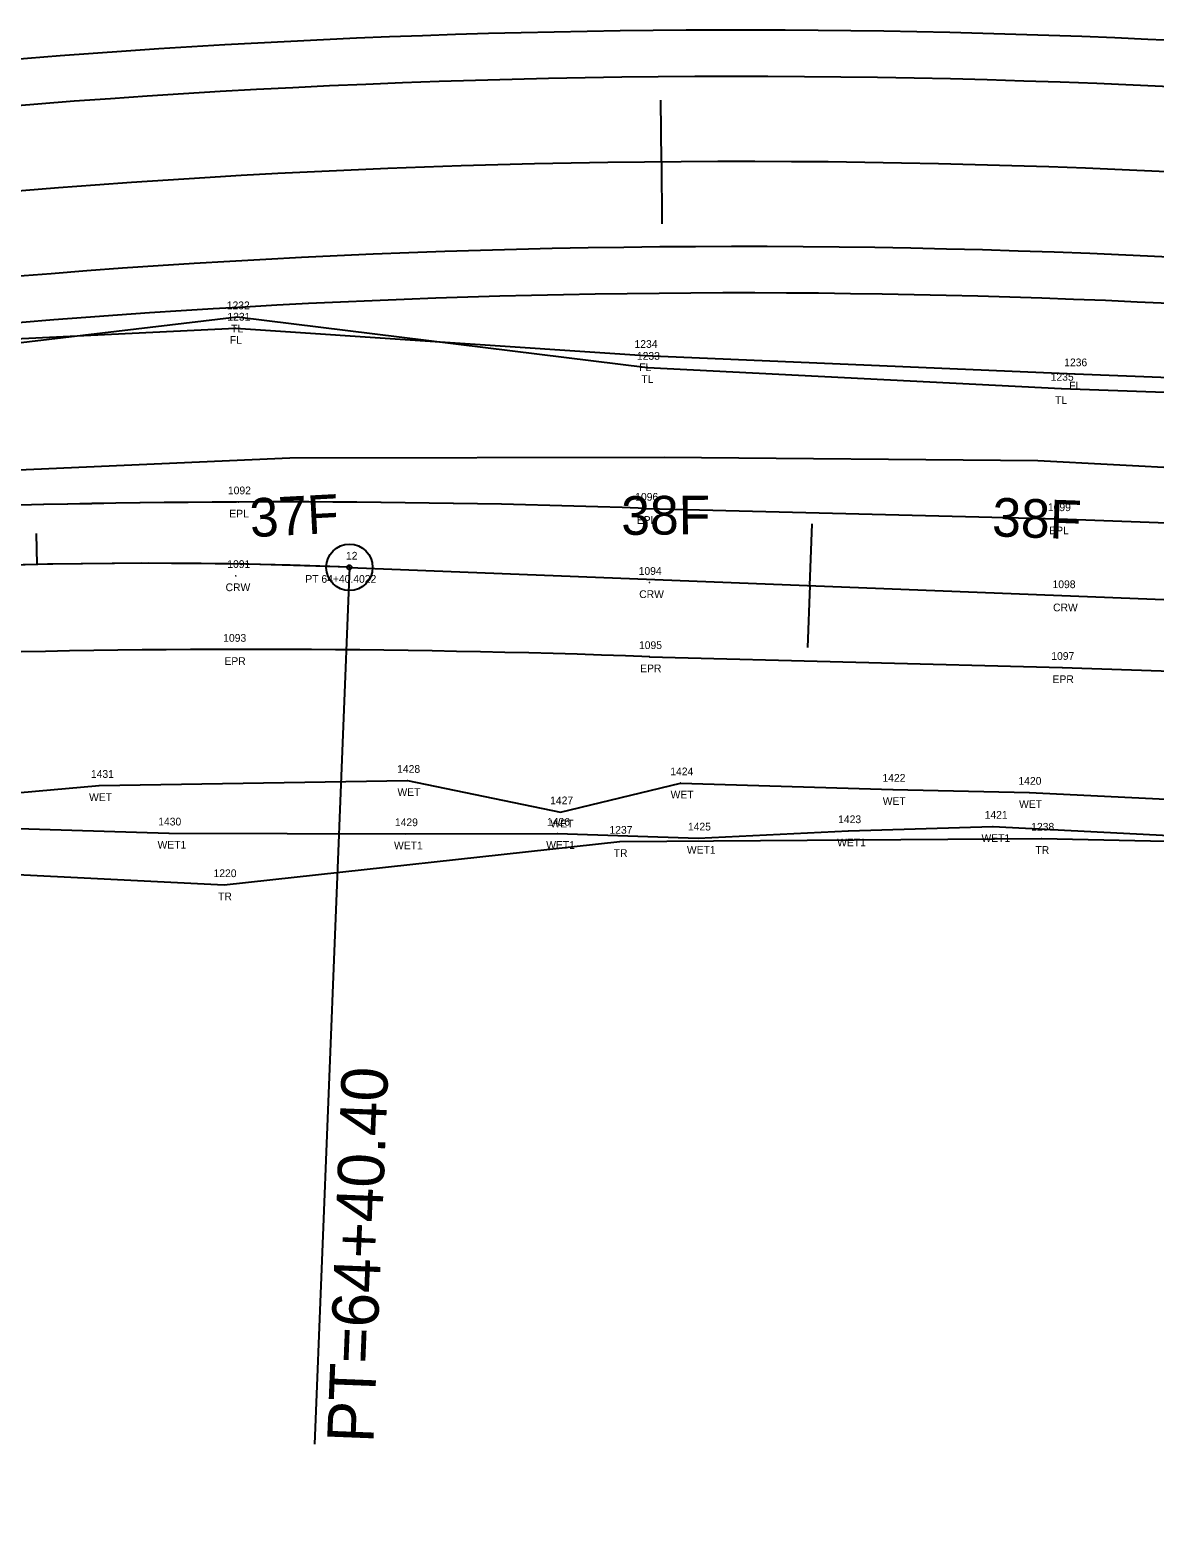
# Model space of a CAD drawing. Extents: x 1964982 to 1970452, y 1116335 to 1119906.
# Drawn here: x 1968079 to 1968224.5, y 1117805.4 to 1118000.4 of the extents above; entities that cross this region are included whole.
import ezdxf

# ---------------------------------------------------------------- set-up
doc = ezdxf.new("R2010")
doc.units = 0
for name, color, linetype in [('RD_EX_DV_Prop', 7, 'Continuous'), ('RD_EX_Fence_Other', 7, 'Continuous'), ('RD_EX_Fence_Other_txCode', 7, 'Continuous'), ('RD_EX_H2O_WetLd', 7, 'Continuous'), ('RD_EX_H2O_WetLd_txCode', 7, 'Continuous'), ('RD_EX_Road', 7, 'Continuous'), ('RD_EX_Road_txCode', 7, 'Continuous'), ('RD_EX_RW', 7, 'Continuous'), ('RD_EX_VEG', 7, 'Continuous'), ('RD_EX_VEG_txCode', 7, 'Continuous'), ('RD_HC_CL', 7, 'Continuous'), ('RD_HC_CL_Rel', 7, 'Continuous'), ('RD_HC_Data', 7, 'Continuous'), ('RD_HC_Data_Tic', 7, 'Continuous'), ('RD_HC_Data_Tic_Rel', 7, 'Continuous'), ('RD_HC_txCode', 7, 'Continuous'), ('RD_PD_CstnLmt', 7, 'Continuous'), ('RD_PD_Final_TrvlWay', 7, 'Continuous'), ('RD_PD_TX_CstnLmt', 7, 'Continuous'), ('RD_QTY_GR', 7, 'Continuous'), ('RD_SMD_Locator', 7, 'Continuous'), ('RD_SMD_Misc', 7, 'Continuous')]:
    doc.layers.add(name, color=color, linetype=linetype)

msp = doc.modelspace()

# ---------------------------------------------------------------- linework, layer by layer
at = {"layer": 'RD_EX_DV_Prop'}
msp.add_line((1968120.33, 1117930.94), (1968371.35, 1117920.98), dxfattribs=at)
msp.add_arc((1968094.39, 1117277.53), 653.93, 87.72663, 109.21172, dxfattribs=at)
at = {"layer": 'RD_EX_Fence_Other'}
msp.add_lwpolyline([(1967945.93, 1117995.37), (1967947.71, 1117952.52), (1967966.69, 1117955.54), (1968009.98, 1117960.51), (1968062.77, 1117959.8), (1968105.6, 1117961.86), (1968158.55, 1117958.33), (1968214.15, 1117955.95), (1968422.33, 1117947.89), (1968537.53, 1117942.88)], dxfattribs=at)
at = {"layer": 'RD_EX_H2O_WetLd'}
for points in [[(1967871.9, 1117823.22), (1967882.77, 1117820.95), (1967892.49, 1117817.57), (1967903.12, 1117821.47), (1967929.31, 1117838.9), (1967950.71, 1117852.83), (1967976.12, 1117865.5), (1968009.37, 1117883.81), (1968032.7, 1117893.9), (1968056.92, 1117899.97), (1968087.96, 1117902.71), (1968127.85, 1117903.36), (1968147.64, 1117899.29), (1968163.17, 1117903.04), (1968190.62, 1117902.21), (1968208.25, 1117901.82), (1968234.81, 1117900.5)], [(1967873.8, 1117813.35), (1967880.72, 1117811.81), (1967886.54, 1117810.11), (1967895.47, 1117810.58), (1967906.3, 1117816.05), (1967938.67, 1117833.57), (1967956.67, 1117840.55), (1967984.36, 1117856.79), (1968002.89, 1117867.52), (1968020.4, 1117877.91), (1968037.49, 1117884.16), (1968057.43, 1117895.18), (1968076.04, 1117897.19), (1968096.98, 1117896.55), (1968127.56, 1117896.46), (1968147.25, 1117896.52), (1968165.45, 1117895.9), (1968184.88, 1117896.85), (1968203.56, 1117897.42), (1968232.27, 1117895.94)]]:
    msp.add_lwpolyline(points, dxfattribs=at)
at = {"layer": 'RD_EX_Road'}
for points in [[(1968158.7, 1117938.56), (1968212.05, 1117937.21), (1968318.79, 1117933.28), (1968422.76, 1117929.93), (1968530.54, 1117925.7)], [(1968159.16, 1117919.37), (1968212.5, 1117917.97), (1968317.55, 1117914.44), (1968421.52, 1117910.75), (1968527.82, 1117906.41)]]:
    msp.add_lwpolyline(points, dxfattribs=at)
for centre, radius, start, end in [((1968111.4, 1116608.55), 1330.85, 87.96323, 92.25904), ((1968107.56, 1116504.27), 1416.05, 87.91148, 91.95976)]:
    msp.add_arc(centre, radius, start, end, dxfattribs=at)
at = {"layer": 'RD_EX_RW'}
for points in [[(1968158.7, 1117938.56), (1968212.05, 1117937.21), (1968318.79, 1117933.28), (1968422.76, 1117929.93), (1968530.54, 1117925.7)], [(1968159.16, 1117919.37), (1968212.5, 1117917.97), (1968317.55, 1117914.44), (1968421.52, 1117910.75), (1968527.82, 1117906.41)]]:
    msp.add_lwpolyline(points, dxfattribs=at)
for centre, radius, start, end in [((1968111.4, 1116608.55), 1330.85, 87.96323, 92.25762), ((1968107.56, 1116504.27), 1416.05, 87.91148, 91.95976)]:
    msp.add_arc(centre, radius, start, end, dxfattribs=at)
at = {"layer": 'RD_EX_VEG'}
for points in [[(1967422.03, 1117809.72), (1967453.38, 1117748.92), (1967559.8, 1117796.17), (1967844.47, 1117917.07), (1967917.86, 1117947.25), (1968009.67, 1117958.84), (1968061.48, 1117958.08), (1968105.8, 1117963.33), (1968158.86, 1117956.79), (1968212.37, 1117954.08), (1968423.16, 1117946.63), (1968536.42, 1117942.26)], [(1967303.54, 1117601.01), (1967338.99, 1117640.22), (1967353.28, 1117654.56), (1967394.76, 1117667.24), (1967484.61, 1117707.66), (1967711.58, 1117796.67), (1967890.09, 1117864.21), (1967929.29, 1117872.68), (1967959.15, 1117877.99), (1967976.93, 1117884.5), (1968014.32, 1117894.35), (1968104.14, 1117889.87), (1968155.31, 1117895.48), (1968209.85, 1117895.88), (1968320.55, 1117893.51), (1968423.04, 1117892.22), (1968529.15, 1117876.96)]]:
    msp.add_lwpolyline(points, dxfattribs=at)
at = {"layer": 'RD_HC_CL'}
msp.add_line((1968120.33, 1117930.94), (1969279.02, 1117884.95), dxfattribs=at)
msp.add_arc((1968094.39, 1117277.53), 653.93, 87.72663, 111.99584, dxfattribs=at)
at = {"layer": 'RD_HC_CL_Rel'}
msp.add_arc((1968170.83, 1116837.51), 1145.92, 84.66612, 115.04633, dxfattribs=at)
at = {"layer": 'RD_HC_Data'}
msp.add_line((1968120.33, 1117930.94), (1968115.83, 1117817.52), dxfattribs=at)
for radius in [3, 0.282]:
    msp.add_circle((1968120.33, 1117930.94), radius, dxfattribs=at)
at = {"layer": 'RD_HC_Data_Tic'}
for p, q in [((1968079.94, 1117931.3), (1968079.85, 1117935.3)), ((1968179.88, 1117928.58), (1968180.2, 1117936.57)), ((1968179.88, 1117928.58), (1968179.56, 1117920.59))]:
    msp.add_line(p, q, dxfattribs=at)
at = {"layer": 'RD_HC_Data_Tic_Rel'}
for q in [(1968160.61, 1117991.38), (1968160.75, 1117975.38)]:
    msp.add_line((1968160.68, 1117983.38), q, dxfattribs=at)
at = {"layer": 'RD_PD_CstnLmt'}
for p, q in [((1968064.24, 1117942.97), (1968112.64, 1117945.12)), ((1968112.64, 1117945.12), (1968161.02, 1117945.18)), ((1968161.02, 1117945.18), (1968209.35, 1117944.76)), ((1968209.35, 1117944.76), (1968257.63, 1117942.17))]:
    msp.add_line(p, q, dxfattribs=at)
at = {"layer": 'RD_PD_Final_TrvlWay'}
for radius in [1156.92, 1134.92]:
    msp.add_arc((1968170.83, 1116837.51), radius, 84.66612, 99.65724, dxfattribs=at)
at = {"layer": 'RD_QTY_GR'}
for radius, end in [(1162.92, 98.1201), (1128.92, 98.06898)]:
    msp.add_arc((1968170.83, 1116837.51), radius, 84.66612, end, dxfattribs=at)
at = {"layer": 'RD_SMD_Locator'}
for centre in [(1968105.8, 1117963.33), (1968105.6, 1117961.86), (1968158.55, 1117958.33), (1968158.86, 1117956.79), (1968214.15, 1117955.95), (1968212.37, 1117954.08), (1968105.99, 1117939.39), (1968158.7, 1117938.56), (1968212.05, 1117937.21), (1968120.33, 1117930.94), (1968105.63, 1117929.86), (1968159.12, 1117928.97), (1968212.65, 1117927.25), (1968105.39, 1117920.31), (1968159.16, 1117919.37), (1968212.5, 1117917.97), (1968087.96, 1117902.71), (1968127.85, 1117903.36), (1968163.17, 1117903.04), (1968190.62, 1117902.21), (1968208.25, 1117901.82), (1968147.64, 1117899.29), (1968096.98, 1117896.55), (1968127.56, 1117896.46), (1968147.25, 1117896.52), (1968165.45, 1117895.9), (1968184.88, 1117896.85), (1968203.56, 1117897.42), (1968209.85, 1117895.88), (1968155.31, 1117895.48), (1968104.14, 1117889.87)]:
    msp.add_circle(centre, 0.001, dxfattribs=at)

# ---------------------------------------------------------------- texts
at = {"layer": 'RD_EX_Fence_Other_txCode'}
for s, p in [('1231', (1968104.54, 1117962.86)), ('FL', (1968104.87, 1117959.86)), ('1234', (1968157.2, 1117959.33)), ('FL', (1968157.82, 1117956.33)), ('1236', (1968212.78, 1117956.95)), ('FL', (1968213.42, 1117953.95))]:
    msp.add_text(s, height=1, dxfattribs=at).set_placement(p)
at = {"layer": 'RD_EX_H2O_WetLd_txCode'}
for s, p in [('1431', (1968086.89, 1117903.71)), ('1428', (1968126.5, 1117904.36)), ('1424', (1968161.83, 1117904.04)), ('1422', (1968189.27, 1117903.21)), ('1420', (1968206.86, 1117902.82)), ('WET', (1968086.65, 1117900.71)), ('WET', (1968126.54, 1117901.36)), ('WET', (1968161.87, 1117901.04)), ('1427', (1968146.29, 1117900.29)), ('WET', (1968189.31, 1117900.21)), ('WET', (1968206.94, 1117899.82)), ('1430', (1968095.6, 1117897.55)), ('1429', (1968126.21, 1117897.46)), ('1426', (1968145.88, 1117897.52)), ('WET', (1968146.33, 1117897.29)), ('1425', (1968164.11, 1117896.9)), ('1423', (1968183.54, 1117897.85)), ('1421', (1968202.49, 1117898.42)), ('WET1', (1968183.41, 1117894.85)), ('WET1', (1968202.08, 1117895.42)), ('WET1', (1968095.51, 1117894.55)), ('WET1', (1968126.09, 1117894.46)), ('WET1', (1968145.78, 1117894.52)), ('WET1', (1968163.98, 1117893.9))]:
    msp.add_text(s, height=1, dxfattribs=at).set_placement(p)
at = {"layer": 'RD_EX_Road_txCode'}
for s, p in [('1092', (1968104.61, 1117940.39)), ('1096', (1968157.29, 1117939.56)), ('1099', (1968210.67, 1117938.21)), ('EPL', (1968104.79, 1117937.39)), ('EPL', (1968157.5, 1117936.56)), ('EPL', (1968210.85, 1117935.21)), ('1093', (1968104, 1117921.31)), ('1095', (1968157.78, 1117920.37)), ('EPR', (1968104.16, 1117918.31)), ('1097', (1968211.11, 1117918.97)), ('EPR', (1968157.93, 1117917.37)), ('EPR', (1968211.27, 1117915.97))]:
    msp.add_text(s, height=1, dxfattribs=at).set_placement(p)
at = {"layer": 'RD_EX_VEG_txCode'}
for s, p in [('1232', (1968104.46, 1117964.33)), ('TL', (1968105.03, 1117961.33)), ('1233', (1968157.51, 1117957.79)), ('TL', (1968158.09, 1117954.79)), ('1235', (1968211.03, 1117955.08)), ('TL', (1968211.6, 1117952.08)), ('1238', (1968208.51, 1117896.88)), ('1237', (1968153.96, 1117896.48)), ('TR', (1968154.51, 1117893.48)), ('TR', (1968209.06, 1117893.88)), ('1220', (1968102.75, 1117890.87)), ('TR', (1968103.34, 1117887.87))]:
    msp.add_text(s, height=1, dxfattribs=at).set_placement(p)
at = {"layer": 'RD_HC_Data'}
msp.add_text('PT=64+40.40', height=6, rotation=87.7266, dxfattribs=at).set_placement((1968123.43, 1117817.61))
at = {"layer": 'RD_HC_txCode'}
for s, p in [('12', (1968119.88, 1117931.94)), ('PT 64+40.4022', (1968114.62, 1117928.94))]:
    msp.add_text(s, height=1, dxfattribs=at).set_placement(p)
at = {"layer": 'RD_PD_TX_CstnLmt'}
for s, rotation, p in [('37F', 3.0072, (1968107.56, 1117934.83)), ('38F', 0.5072, (1968155.5, 1117935.13)), ('38F', 358.0072, (1968203.4, 1117934.96))]:
    msp.add_text(s, height=5, rotation=rotation, dxfattribs=at).set_placement(p)
at = {"layer": 'RD_SMD_Misc'}
for s, p in [('1091', (1968104.53, 1117930.86)), ('1094', (1968157.74, 1117929.97)), ('CRW', (1968104.31, 1117927.86)), ('1098', (1968211.27, 1117928.25)), ('CRW', (1968157.81, 1117926.97)), ('CRW', (1968211.34, 1117925.25))]:
    msp.add_text(s, height=1, dxfattribs=at).set_placement(p)

doc.saveas('drawing.dxf')
